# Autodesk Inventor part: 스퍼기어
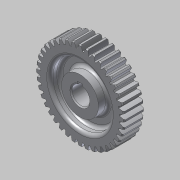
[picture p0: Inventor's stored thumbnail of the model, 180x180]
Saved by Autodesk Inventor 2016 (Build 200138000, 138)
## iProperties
Created: 2018-11
Part Number: 스퍼기어
Material: 알루미늄 6061
Document SubType Name: Modeling
Designer: mduedu
Categories: <?xml version="1.0" encoding="UTF-16"?> <MemberInstance><Categories><FamilyTemplate><FamilyTemplateParameter ValueType="xs:double" Id="1" ObjectReferenceKey="da
Density: 1 g/cm^3
Appearance: 알루미늄 - 평지
CustomPartVersion: 1
Author: mduedu
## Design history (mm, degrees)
sketch "Sketch1"
  geometry: C1 r 42 at (0, 0)
  constraints: 1 centre point
  dimensions: "d0" = 83.99905 diameter of C1 (= da_da)
extrude "Extrusion1" new body sketch "Sketch1" distance "d1" = 19 (= da_b); taper "d2" = 0 deg
workplane "Work Plane2"
sketch "Sketch2"
  geometry: C1 r 42 at (0, 0) reference; C2 r 40.05 at (0, 0)
  constraints: 1 centre point, 1 coincident
  dimensions: "d3" = 80.10038 diameter of C2 (= da_dw)
feature "피치 지름" sketch "Sketch2" dims "d4" = 10, "d5" = 0
workplane "Work Plane8"
workplane "Work Plane9"
feature "스퍼 기어" dims "da_b" = 19, "da_d" = 80, "da_aw" = 80.10038, "da_da" = 83.99905, "da_df" = 75, "da_dw" = 80.10038, angle "da_beta" = 0 deg, "da_lefttooth" = 0, "da_righttooth" = 0
sketch "스케치3"
  geometry: L1 (-42, 19)-(42, 19) reference; L2 (42, 19)-(42, 0) reference; L3 (42, 0)-(-42, 0) reference; L4 (-42, 0)-(-42, 19) reference; L5 (0, 0)-(0, 19); L6 (42, 0)-(41, 0); L7 (42, 1)-(42, 0); L8 (42, 19)-(41, 19); L9 (42, 18)-(42, 19); L10 (41, 19)-(42, 18); L11 (41, 0)-(42, 1)
  constraints: 14 end point, 2 horizontal, 2 vertical, 1 midpoint
  dimensions: "d49" = 1 distance from line of L8.end L2; "d50" = 1 horizontal distance of L8.end L9.start; "d51" = 1 horizontal distance of L6.end L7.start; "d52" = 1 horizontal distance of L6.end L7.start
revolve "회전1" sketch "스케치3" stored, may be unused: angle "d53" = 90 deg
sketch "스케치4"
  geometry: L1 (-2.5, 8.124)-(2.5, 8.124); L2 (2.5, 8.124)-(2.5, 10.8); L3 (2.5, 10.8)-(-2.5, 10.8); L4 (-2.5, 10.8)-(-2.5, 8.124); A1 r 8.5 centre (0, 0) between (-2.5, 8.124) and (2.5, 8.124); 1 further point
  constraints: 8 end point, 2 parallel, 2 point on circle, 1 centre point, 1 coincident, 1 horizontal, 1 perpendicular
  dimensions: "d54" = 17 diameter of A1; "d56" = 19.3 dimension on A1 L3; "d57" = 5 distance of L2.end L3.end
extrude "돌출2" cut sketch "스케치4" stored distance "d58" = 10; taper "d59" = 0 deg
chamfer "모따기1" distance "d60" = 1; stored, may be unused: second distance "d61" = 2, angle "d62" = 45 deg
sketch "스케치5"
  geometry: C1 r 17.5 at (0, 0); C2 r 28.5 at (0, 0); 1 further point
  constraints: 2 centre point, 2 coincident
  dimensions: "d63" = 35 diameter of C1; "d64" = 57 diameter of C2
extrude "돌출3" cut sketch "스케치5" distance "d65" = 9.5; taper "d66" = 0 deg
fillet "모깎기1" dims "d67" = 3
body "Solid1"
body "Srf1"
node "절단 모서리 투영1"
other parameters: "d16" = 80.10038 (= da_aw), "d17" = 0, "d34" = 4.5 deg (computed from da_z), "d39" = 0, "d41" = 0, "d43" = 80.10038 (= da_aw), "d46" = 80.10038 (= da_aw), "d47" = 0, "d48" = 0
